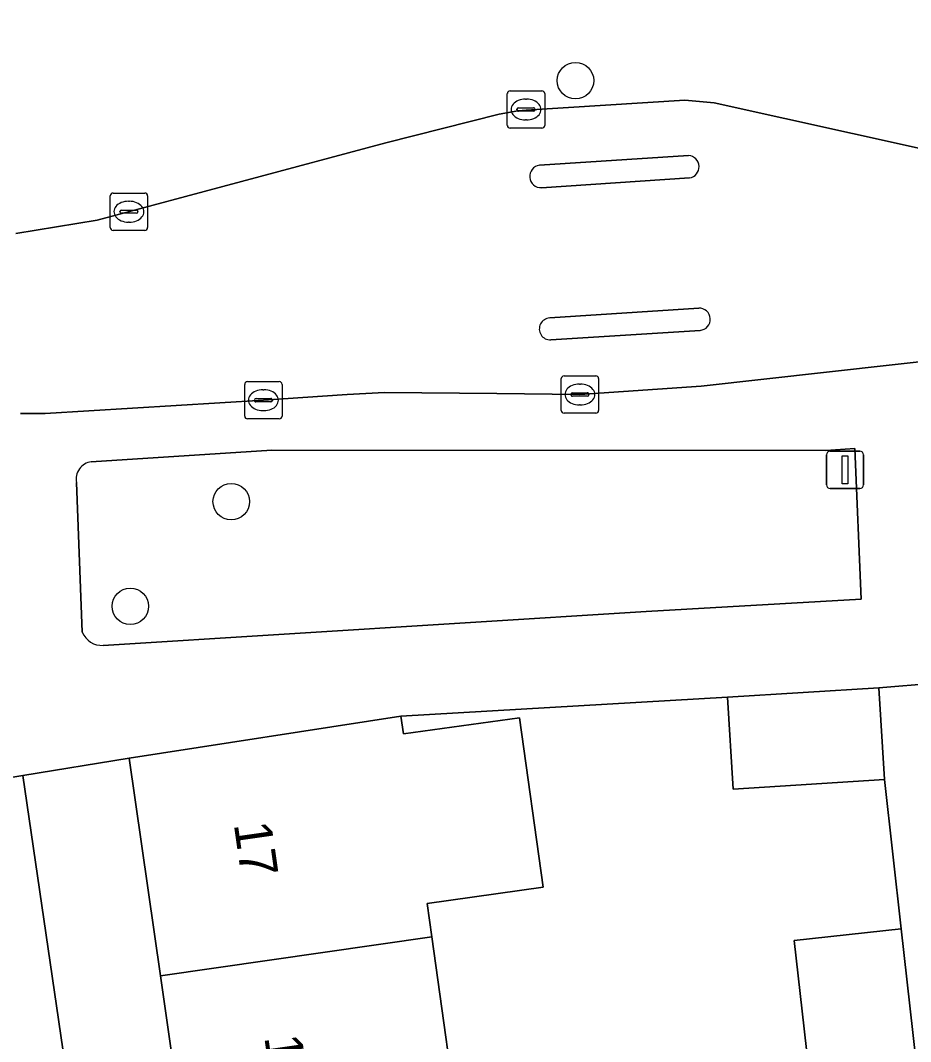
# Model space of a CAD drawing. Extents: x 159053 to 160042, y 380449 to 381423.
# Drawn here: x 159505.24 to 159529.09, y 381158.52 to 381185.89 of the extents above; entities that cross this region are included whole.
import ezdxf

# ---------------------------------------------------------------- set-up
doc = ezdxf.new("R2010")
doc.units = 0
for name, color, linetype in [('IMGEO_Boom', 7, 'Continuous'), ('IMGEO_Erf', 7, 'Continuous'), ('IMGEO_Groenvoorziening', 7, 'Continuous'), ('IMGEO_Kolk', 7, 'Continuous'), ('IMGEO_Lichtmast', 7, 'Continuous'), ('IMGEO_Muur', 7, 'Continuous'), ('IMGEO_Pand', 7, 'Continuous'), ('IMGEO_Pand_nummerreeks', 7, 'Continuous'), ('IMGEO_Rijbaan_lokaal_open', 7, 'Continuous'), ('IMGEO_Verkeerseiland_open', 7, 'Continuous'), ('IMGEO_Voetpad_open', 7, 'Continuous')]:
    doc.layers.add(name, color=color, linetype=linetype)

msp = doc.modelspace()

# ---------------------------------------------------------------- linework, layer by layer
at = {"layer": 'IMGEO_Boom'}
for centre in [(159520.115, 381184.275), (159510.891, 381172.991), (159508.187, 381170.185)]:
    msp.add_circle(centre, 0.489, dxfattribs=at)
at = {"layer": 'IMGEO_Erf'}
msp.add_lwpolyline([(159526.517, 381156.405), (159525.977, 381161.221), (159528.842, 381161.542), (159528.395, 381165.537), (159524.339, 381165.286), (159524.187, 381167.748), (159515.439, 381167.238), (159515.505, 381166.765), (159518.611, 381167.198), (159519.245, 381162.652), (159516.139, 381162.219), (159516.264, 381161.323), (159517.058, 381155.627)], dxfattribs=at)
msp.add_lwpolyline([(159513.074, 381131.819), (159512.258, 381137.51), (159511.442, 381143.203), (159510.626, 381148.894), (159509.811, 381154.586), (159508.995, 381160.278), (159508.158, 381166.116), (159505.308, 381165.647), (159513.151, 381111.974), (159517.559, 381112.218), (159517.211, 381114.836), (159515.542, 381114.597), (159514.705, 381120.436), (159513.889, 381126.127)], close=True, dxfattribs=at)
at = {"layer": 'IMGEO_Groenvoorziening'}
for points in [[(159527.598, 381174.411), (159526.826, 381174.358), (159511.982, 381174.372), (159507.138, 381174.06)], [(159507.464, 381169.136), (159522.011, 381170.042), (159527.774, 381170.374), (159527.598, 381174.411)], [(159506.744, 381173.501), (159506.898, 381169.489)]]:
    msp.add_lwpolyline(points, dxfattribs=at)
for centre, radius, start, end in [((159507.209, 381173.592), 0.474, 98.5957, 191.0496), ((159507.429, 381169.711), 0.576, 202.6549, 273.4436)]:
    msp.add_arc(centre, radius, start, end, dxfattribs=at)
at = {"layer": 'IMGEO_Kolk'}
for p, q in [((159518.289, 381183.075), (159518.289, 381183.927)), ((159518.364, 381184.001), (159519.216, 381184.001)), ((159519.29, 381183.927), (159519.29, 381183.075)), ((159518.777, 381183.781), (159518.802, 381183.781)), ((159518.548, 381183.495), (159518.548, 381183.507)), ((159518.986, 381183.458), (159518.588, 381183.458)), ((159518.591, 381183.544), (159518.989, 381183.544)), ((159519.032, 381183.507), (159519.032, 381183.495)), ((159518.8, 381183.221), (159518.775, 381183.221)), ((159519.216, 381183.001), (159518.364, 381183.001)), ((159507.724, 381181.262), (159508.576, 381181.262)), ((159507.649, 381180.336), (159507.649, 381181.188)), ((159508.137, 381181.042), (159508.162, 381181.042)), ((159508.65, 381181.188), (159508.65, 381180.336)), ((159507.908, 381180.756), (159507.908, 381180.768)), ((159508.346, 381180.719), (159507.948, 381180.719)), ((159507.951, 381180.805), (159508.349, 381180.805)), ((159508.392, 381180.768), (159508.392, 381180.756)), ((159508.16, 381180.482), (159508.135, 381180.482)), ((159508.576, 381180.262), (159507.724, 381180.262)), ((159519.733, 381175.435), (159519.733, 381176.287)), ((159519.808, 381176.361), (159520.66, 381176.361)), ((159520.734, 381176.287), (159520.734, 381175.435)), ((159511.253, 381175.282), (159511.253, 381176.134)), ((159511.328, 381176.208), (159512.18, 381176.208)), ((159511.741, 381175.988), (159511.766, 381175.988)), ((159512.254, 381176.134), (159512.254, 381175.282)), ((159520.221, 381176.141), (159520.246, 381176.141)), ((159511.512, 381175.702), (159511.512, 381175.714)), ((159511.555, 381175.751), (159511.953, 381175.751)), ((159511.996, 381175.714), (159511.996, 381175.702)), ((159519.992, 381175.855), (159519.992, 381175.867)), ((159520.43, 381175.818), (159520.032, 381175.818)), ((159520.035, 381175.904), (159520.433, 381175.904)), ((159520.476, 381175.867), (159520.476, 381175.855)), ((159511.95, 381175.665), (159511.552, 381175.665)), ((159520.244, 381175.581), (159520.219, 381175.581)), ((159512.18, 381175.208), (159511.328, 381175.208)), ((159511.764, 381175.428), (159511.739, 381175.428)), ((159520.66, 381175.361), (159519.808, 381175.361))]:
    msp.add_line(p, q, dxfattribs=at)
for points in [[(159518.289, 381183.075), (159518.289, 381183.927)], [(159518.364, 381184.001), (159519.216, 381184.001)], [(159519.29, 381183.927), (159519.29, 381183.075)], [(159519.216, 381183.001), (159518.364, 381183.001)], [(159507.724, 381181.262), (159508.576, 381181.262)], [(159507.649, 381180.336), (159507.649, 381181.188)], [(159508.65, 381181.188), (159508.65, 381180.336)], [(159508.576, 381180.262), (159507.724, 381180.262)], [(159519.733, 381175.435), (159519.733, 381176.287)], [(159519.808, 381176.361), (159520.66, 381176.361)], [(159520.734, 381176.287), (159520.734, 381175.435)], [(159511.253, 381175.282), (159511.253, 381176.134)], [(159511.328, 381176.208), (159512.18, 381176.208)], [(159512.254, 381176.134), (159512.254, 381175.282)], [(159512.18, 381175.208), (159511.328, 381175.208)], [(159520.66, 381175.361), (159519.808, 381175.361)]]:
    msp.add_lwpolyline(points, dxfattribs=at)
for centre, radius, start, end in [((159518.366, 381183.925), 0.0765, 91.552, 178.448), ((159518.366, 381183.925), 0.0765, 91.552, 178.448), ((159519.214, 381183.925), 0.0765, 1.552, 88.448), ((159519.214, 381183.925), 0.0765, 1.552, 88.448), ((159518.588, 381183.504), 0.0403, 85.8775, 175.7526), ((159518.585, 381183.494), 0.0366, 178.938, 274.7102), ((159518.989, 381183.501), 0.043, 264.8664, 352.4533), ((159518.993, 381183.506), 0.0386, 1.7309, 96.639), ((159518.366, 381183.077), 0.0765, 181.552, 268.448), ((159518.366, 381183.077), 0.0765, 181.552, 268.448), ((159519.214, 381183.077), 0.0765, 271.552, 358.448), ((159519.214, 381183.077), 0.0765, 271.552, 358.448), ((159507.726, 381181.186), 0.0765, 91.552, 178.448), ((159507.726, 381181.186), 0.0765, 91.552, 178.448), ((159508.574, 381181.186), 0.0765, 1.552, 88.448), ((159508.574, 381181.186), 0.0765, 1.552, 88.448), ((159507.948, 381180.765), 0.0403, 85.8775, 175.7526), ((159507.945, 381180.755), 0.0366, 178.938, 274.7102), ((159508.349, 381180.762), 0.043, 264.8664, 352.4533), ((159508.353, 381180.767), 0.0386, 1.7309, 96.639), ((159507.726, 381180.338), 0.0765, 181.552, 268.448), ((159507.726, 381180.338), 0.0765, 181.552, 268.448), ((159508.574, 381180.338), 0.0765, 271.552, 358.448), ((159508.574, 381180.338), 0.0765, 271.552, 358.448), ((159519.81, 381176.285), 0.0765, 91.552, 178.448), ((159519.81, 381176.285), 0.0765, 91.552, 178.448), ((159520.658, 381176.285), 0.0765, 1.552, 88.448), ((159520.658, 381176.285), 0.0765, 1.552, 88.448), ((159511.33, 381176.132), 0.0765, 91.552, 178.448), ((159511.33, 381176.132), 0.0765, 91.552, 178.448), ((159512.178, 381176.132), 0.0765, 1.552, 88.448), ((159512.178, 381176.132), 0.0765, 1.552, 88.448), ((159511.552, 381175.711), 0.0403, 85.8775, 175.7526), ((159511.957, 381175.713), 0.0386, 1.7309, 96.639), ((159520.032, 381175.864), 0.0403, 85.8775, 175.7526), ((159520.029, 381175.854), 0.0366, 178.938, 274.7102), ((159520.433, 381175.861), 0.043, 264.8664, 352.4533), ((159520.437, 381175.866), 0.0386, 1.7309, 96.639), ((159511.549, 381175.701), 0.0366, 178.938, 274.7102), ((159511.953, 381175.708), 0.043, 264.8664, 352.4533), ((159511.33, 381175.284), 0.0765, 181.552, 268.448), ((159511.33, 381175.284), 0.0765, 181.552, 268.448), ((159512.178, 381175.284), 0.0765, 271.552, 358.448), ((159512.178, 381175.284), 0.0765, 271.552, 358.448), ((159519.81, 381175.437), 0.0765, 181.552, 268.448), ((159519.81, 381175.437), 0.0765, 181.552, 268.448), ((159520.658, 381175.437), 0.0765, 271.552, 358.448), ((159520.658, 381175.437), 0.0765, 271.552, 358.448)]:
    msp.add_arc(centre, radius, start, end, dxfattribs=at)
for centre, major_axis, ratio, start_param, end_param in [((159518.776, 381183.501), (-0.387, 0.002), 0.722429, 4.712389, 7.853982), ((159518.801, 381183.501), (-0.39, 0.002), 0.717154, 1.570796, 4.712389), ((159508.136, 381180.762), (-0.387, 0.002), 0.722429, 4.712389, 7.853982), ((159508.161, 381180.762), (-0.39, 0.002), 0.717154, 1.570796, 4.712389), ((159511.74, 381175.708), (-0.387, 0.002), 0.722429, 4.712389, 7.853982), ((159511.765, 381175.708), (-0.39, 0.002), 0.717154, 1.570796, 4.712389), ((159520.22, 381175.861), (-0.387, 0.002), 0.722429, 4.712389, 7.853982), ((159520.245, 381175.861), (-0.39, 0.002), 0.717154, 1.570796, 4.712389)]:
    msp.add_ellipse(centre, major_axis=major_axis, ratio=ratio, start_param=start_param, end_param=end_param, dxfattribs=at)
at = {"layer": 'IMGEO_Lichtmast'}
for p, q in [((159526.842, 381173.442), (159526.842, 381174.242)), ((159526.842, 381174.242), (159526.842, 381173.442)), ((159526.942, 381174.342), (159527.732, 381174.342)), ((159527.732, 381174.342), (159526.942, 381174.342)), ((159527.832, 381174.242), (159527.832, 381173.442)), ((159527.832, 381173.442), (159527.832, 381174.242)), ((159527.732, 381173.342), (159526.942, 381173.342)), ((159526.942, 381173.342), (159527.732, 381173.342))]:
    msp.add_line(p, q, dxfattribs=at)
msp.add_lwpolyline([(159527.262, 381174.217), (159527.412, 381174.217), (159527.412, 381173.467), (159527.262, 381173.467), (159527.262, 381174.217)], dxfattribs=at)
for centre, start, end in [((159526.942, 381174.242), 90, 180), ((159526.942, 381174.242), 90, 180), ((159527.732, 381174.242), 0, 90), ((159527.732, 381174.242), 360, 90), ((159526.942, 381173.442), 180, 270), ((159526.942, 381173.442), 180, 270), ((159527.732, 381173.442), 270, 0), ((159527.732, 381173.442), 270, 0)]:
    msp.add_arc(centre, 0.1, start, end, dxfattribs=at)
at = {"layer": 'IMGEO_Muur'}
msp.add_lwpolyline([(159515.439, 381167.238), (159524.187, 381167.748)], dxfattribs=at)
at = {"layer": 'IMGEO_Pand'}
for points in [[(159524.187, 381167.748), (159524.339, 381165.286), (159528.395, 381165.537), (159528.243, 381167.998)], [(159515.439, 381167.238), (159508.158, 381166.116), (159508.995, 381160.278), (159516.264, 381161.323), (159516.139, 381162.219), (159519.245, 381162.652), (159518.611, 381167.198), (159515.505, 381166.765)], [(159526.517, 381156.405), (159529.394, 381156.614), (159528.842, 381161.542), (159525.977, 381161.221)], [(159508.995, 381160.278), (159509.811, 381154.586), (159517.058, 381155.627), (159516.264, 381161.323)]]:
    msp.add_lwpolyline(points, close=True, dxfattribs=at)
at = {"layer": 'IMGEO_Rijbaan_lokaal_open'}
for points in [[(159586.493, 381180.403), (159588.568, 381180.51), (159605.874, 381181.568), (159606.325, 381181.656), (159606.582, 381181.67), (159606.136, 381187.455), (159605.291, 381187.402), (159602.26, 381187.209), (159590.315, 381186.532), (159587.939, 381186.369), (159530.144, 381182.407), (159529.435, 381182.44), (159523.828, 381183.683), (159523.046, 381183.749), (159518.794, 381183.482), (159518.568, 381183.462), (159518.072, 381183.376), (159515.031, 381182.612), (159507.303, 381180.534), (159505.117, 381180.174)], [(159519.15, 381182.009), (159523.147, 381182.266)], [(159523.172, 381181.666), (159519.206, 381181.406)], [(159505.243, 381175.355), (159505.908, 381175.35), (159511.753, 381175.71), (159514, 381175.865), (159514.999, 381175.911), (159518.007, 381175.884), (159520.233, 381175.862), (159523.482, 381176.081), (159530.282, 381176.844), (159530.531, 381176.861), (159534.197, 381177.109), (159549.221, 381178.031), (159550.659, 381178.141), (159551.057, 381178.171)], [(159519.426, 381177.913), (159523.416, 381178.175)], [(159523.454, 381177.581), (159519.455, 381177.325)]]:
    msp.add_lwpolyline(points, dxfattribs=at)
for centre, radius, start, end in [((159523.124, 381181.965), 0.302, 279.1554, 85.6165), ((159519.192, 381181.709), 0.303, 97.934, 272.6775), ((159519.44, 381177.619), 0.294, 92.7215, 272.9255), ((159523.43, 381177.878), 0.298, 274.6291, 92.6917)]:
    msp.add_arc(centre, radius, start, end, dxfattribs=at)
at = {"layer": 'IMGEO_Verkeerseiland_open'}
for points in [[(159523.147, 381182.266), (159519.15, 381182.009)], [(159519.206, 381181.406), (159523.172, 381181.666)], [(159523.416, 381178.175), (159519.426, 381177.913)], [(159519.455, 381177.325), (159523.454, 381177.581)]]:
    msp.add_lwpolyline(points, dxfattribs=at)
for centre, radius, start, end in [((159523.124, 381181.965), 0.302, 279.1554, 85.6165), ((159519.192, 381181.709), 0.303, 97.934, 272.6775), ((159519.44, 381177.619), 0.294, 92.7215, 272.9255), ((159523.43, 381177.878), 0.298, 274.6291, 92.6917)]:
    msp.add_arc(centre, radius, start, end, dxfattribs=at)
at = {"layer": 'IMGEO_Voetpad_open'}
for points in [[(159505.117, 381180.174), (159507.303, 381180.534), (159515.031, 381182.612), (159518.072, 381183.376), (159518.568, 381183.462), (159518.794, 381183.482), (159523.046, 381183.749), (159523.828, 381183.683), (159529.435, 381182.44), (159530.144, 381182.407)], [(159530.531, 381176.861), (159530.282, 381176.844), (159523.482, 381176.081), (159520.233, 381175.862), (159518.007, 381175.884), (159514.999, 381175.911), (159514, 381175.865), (159511.753, 381175.71), (159505.908, 381175.35), (159505.243, 381175.355)], [(159507.138, 381174.06), (159511.982, 381174.372), (159526.826, 381174.358), (159527.598, 381174.411), (159527.774, 381170.374), (159522.011, 381170.042), (159507.464, 381169.136)], [(159506.898, 381169.489), (159506.744, 381173.501)], [(159502.662, 381166.106), (159502.772, 381165.23), (159505.308, 381165.647), (159508.158, 381166.116), (159515.439, 381167.238), (159524.187, 381167.748), (159528.243, 381167.998), (159529.754, 381168.12), (159533.973, 381168.434), (159539.225, 381168.604), (159542.436, 381168.795), (159549.763, 381169.232), (159550.971, 381169.356), (159556.672, 381169.986)], [(159530.756, 381158.212), (159530.317, 381162.208), (159530.025, 381164.867), (159529.934, 381165.699), (159529.754, 381168.12), (159528.243, 381167.998), (159528.395, 381165.537), (159528.842, 381161.542), (159529.394, 381156.614)], [(159536.881, 380989.854), (159536.416, 380989.716), (159536.175, 380990.447), (159531.838, 381003.607), (159526.805, 381019.287), (159526.692, 381019.269), (159526.177, 381022.796), (159513.71, 381108.241), (159513.655, 381108.522), (159513.151, 381111.974), (159505.308, 381165.647), (159502.772, 381165.23), (159505.28, 381148.066)]]:
    msp.add_lwpolyline(points, dxfattribs=at)
for centre, radius, start, end in [((159507.209, 381173.592), 0.474, 98.5957, 191.0496), ((159507.429, 381169.711), 0.576, 202.6549, 273.4436)]:
    msp.add_arc(centre, radius, start, end, dxfattribs=at)

# ---------------------------------------------------------------- texts
at = {"layer": 'IMGEO_Pand_nummerreeks'}
for s, rotation, p in [('17', 278.1587, (159510.958, 381164.346)), ('19', 278.1564, (159511.775, 381158.636))]:
    msp.add_text(s, height=1, rotation=rotation, dxfattribs=at).set_placement(p)

doc.saveas('drawing.dxf')
